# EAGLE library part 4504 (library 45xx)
TTL or CMOS to CMOS hex LEVEL SHIFTER
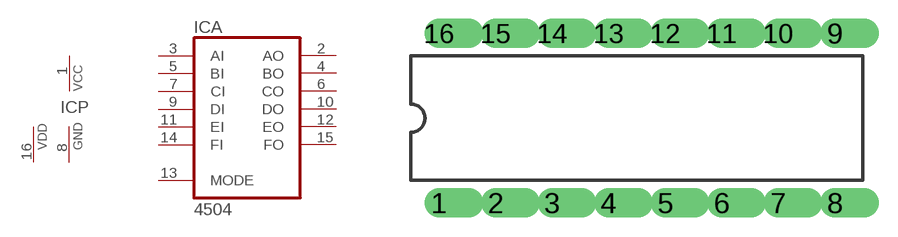
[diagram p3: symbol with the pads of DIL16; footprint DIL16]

Designator prefix IC; gates A=4504 P=PWR+VCC

## 4504N  [DIL16]
1  P:VCC  pwr
2  A:AO  out
3  A:AI  in
4  A:BO  out
5  A:BI  in
6  A:CO  out
7  A:CI  in
8  P:GND  pwr
9  A:DI  in
10  A:DO  out
11  A:EI  in
12  A:EO  out
13  A:MODE  in
14  A:FI  in
15  A:FO  out
16  P:VDD  pwr

## Footprint DIL16 (pad centres in mm)
Dual In Line
drill 0.813 offset: 1 -8.89,-3.81; 2 -6.35,-3.81; 3 -3.81,-3.81; 4 -1.27,-3.81; 5 1.27,-3.81; 6 3.81,-3.81; 7 6.35,-3.81; 8 8.89,-3.81; 9 8.89,3.81; 10 6.35,3.81; 11 3.81,3.81; 12 1.27,3.81; 13 -1.27,3.81; 14 -3.81,3.81; 15 -6.35,3.81; 16 -8.89,3.81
